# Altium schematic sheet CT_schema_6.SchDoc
size 300 x 177 mm
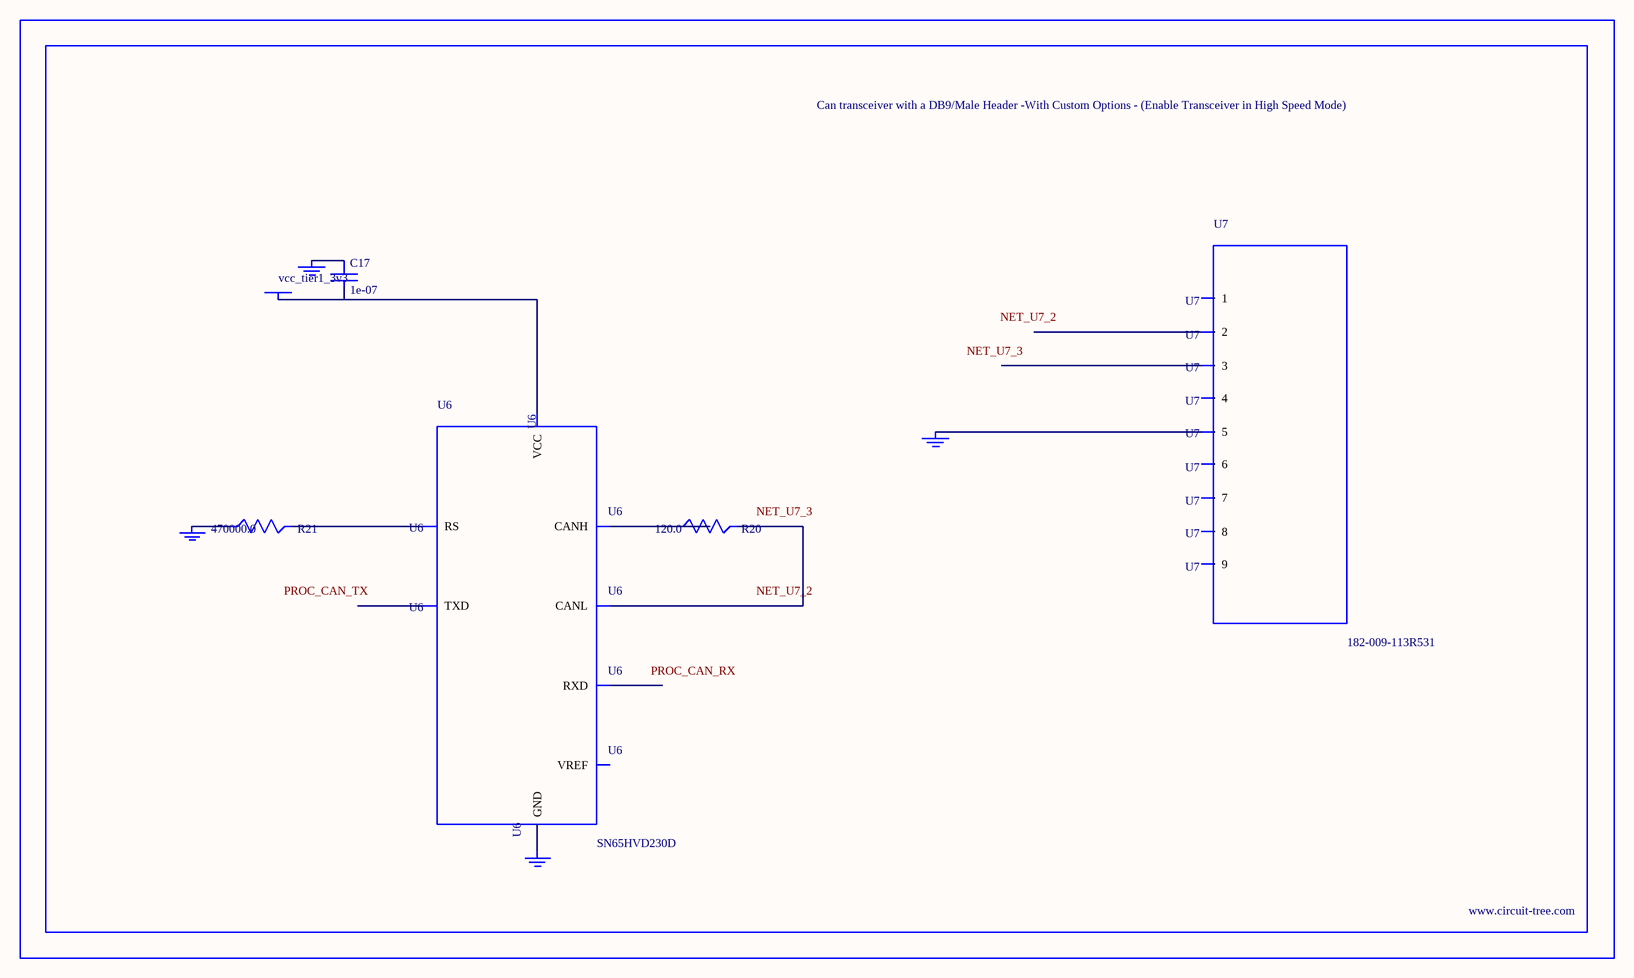
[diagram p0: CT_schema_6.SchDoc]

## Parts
BORDER5  (no value)
C17  1e-07  [C0402]
GND_INSTANCE_5_0  (no value)
GND_INSTANCE_5_1  (no value)
GND_INSTANCE_5_2  (no value)
GND_INSTANCE_5_3  (no value)
POWER_INSTANCE_5_0  vcc_tier1_3v3
R20  120.0  [R0603]
R21  470000.0  [R0603]
U6  SN65HVD230D  [SOIC-8]
U7  182-009-113R531  [182-009-MALE]

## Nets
NetC17_1: C17.1 GND_INSTANCE_5_0.0(GND)
NetC17_2: C17.2 POWER_INSTANCE_5_0.0(PWR) U6.3(VCC)
NetGND_INSTANCE_5_1_0: GND_INSTANCE_5_1.0(GND) R21.1
NetGND_INSTANCE_5_2_0: GND_INSTANCE_5_2.0(GND) U6.2(GND)
NetGND_INSTANCE_5_3_0: GND_INSTANCE_5_3.0(GND) U7.5
NetR20_1: R20.1 U6.7(CANH)
NetR20_2: R20.2 U6.6(CANL)
NetR21_2: R21.2 U6.8(RS)

Not connected (* = marked no-connect by the designer): U6 1(TXD) 4(RXD) 5(VREF); U7 1 2 3 4 6 7 8 9

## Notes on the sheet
- Labels drawn without touching a wire or pin: NET_U7_2, NET_U7_3, PROC_CAN_RX, PROC_CAN_TX

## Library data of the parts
BORDER5 = BORDER_PAGE5
C17 = C0402C104K3RACTU
GND_INSTANCE_5_0-GND_INSTANCE_5_3 = GND
POWER_INSTANCE_5_0 = PWR
R20 = RC0603JR-07120RL
R21 = RC0603JR-07470KL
